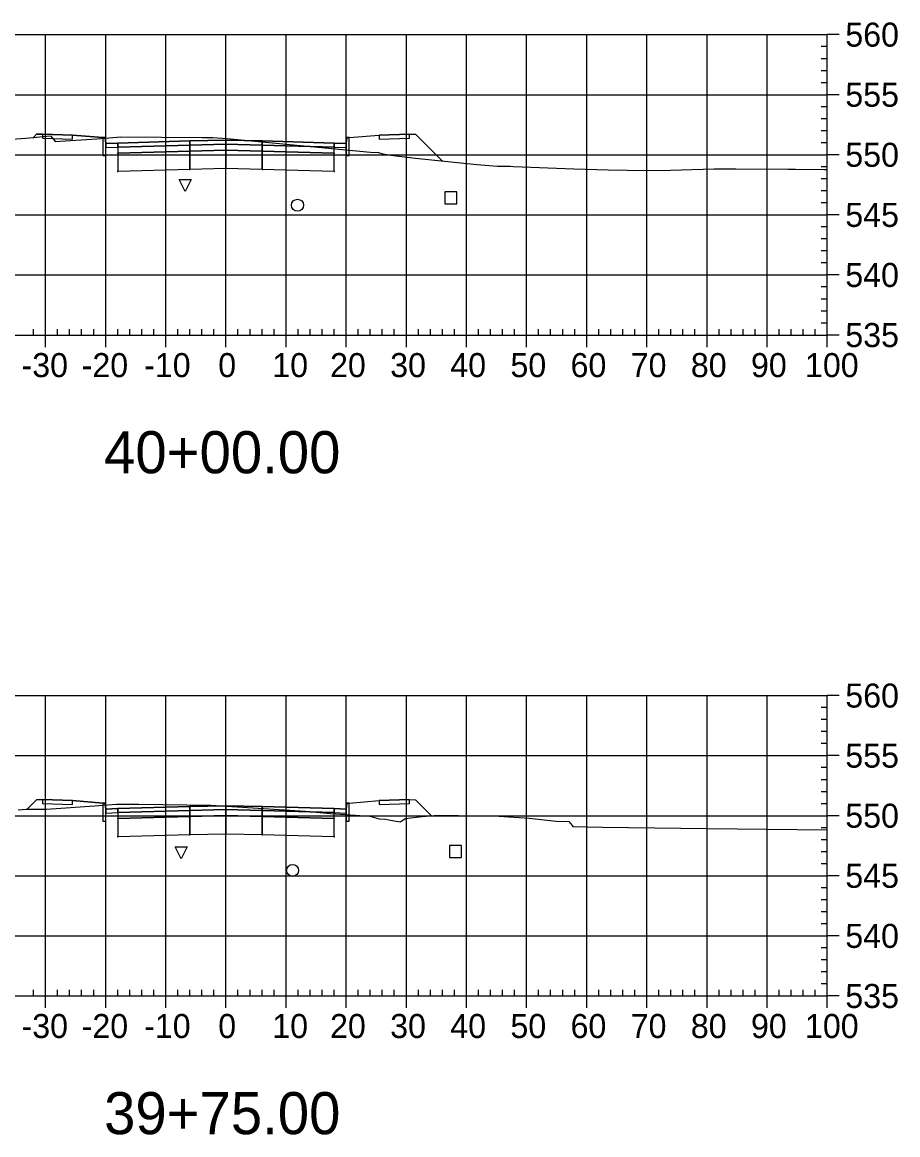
# Model space of a CAD drawing. Extents: x 704834 to 709892, y 372981 to 377533.
# Drawn here: x 709746 to 709891.6, y 376347.7 to 376532.9 of the extents above; entities that cross this region are included whole.
import ezdxf

# ---------------------------------------------------------------- set-up
doc = ezdxf.new("R2010")
doc.units = 0
for name, color, linetype in [('1', 7, 'Continuous'), ('13', 7, 'Continuous'), ('14', 7, 'Continuous'), ('4', 7, 'Continuous'), ('57', 7, 'Continuous'), ('Default_Xsect', 7, 'Continuous'), ('Existing', 7, 'Continuous')]:
    doc.layers.add(name, color=color, linetype=linetype)

msp = doc.modelspace()

# ---------------------------------------------------------------- linework, layer by layer
for points in [[(709748.41, 376514.24), (709747.88, 376513.71)], [(709749.41, 376514.28), (709748.41, 376514.24)], [(709759.41, 376513.68), (709754.41, 376514.08)], [(709800.41, 376513.68), (709805.41, 376514.08)], [(709810.41, 376514.28), (709811.41, 376514.24)], [(709811.41, 376514.24), (709815.85, 376509.81)], [(709748.41, 376403.49), (709746.84, 376401.92)], [(709749.41, 376403.53), (709748.41, 376403.49)], [(709759.41, 376402.93), (709754.41, 376403.33)], [(709800.41, 376402.93), (709805.41, 376403.33)], [(709810.41, 376403.53), (709811.41, 376403.49)], [(709811.41, 376403.49), (709814.1, 376400.81)]]:
    msp.add_lwpolyline(points)
for points in [[(709754.41, 376514.08), (709749.41, 376514.28), (709749.41, 376513.61), (709754.41, 376513.41)], [(709759.91, 376512.68), (709759.83, 376513.68), (709759.41, 376513.68), (709759.41, 376510.68), (709759.91, 376510.68)], [(709799.91, 376510.68), (709800.41, 376510.68), (709800.41, 376513.68), (709800, 376513.68), (709799.91, 376512.68)], [(709805.41, 376513.41), (709810.41, 376513.61), (709810.41, 376514.28), (709805.41, 376514.08)], [(709761.91, 376512.76), (709759.91, 376512.68), (709759.91, 376512.01), (709761.91, 376512.09)], [(709773.91, 376513.12), (709761.91, 376512.76), (709761.91, 376512.09), (709773.91, 376512.45)], [(709773.91, 376512.45), (709761.91, 376512.09), (709761.91, 376511.09), (709773.91, 376511.45)], [(709773.86, 376512.4), (709773.96, 376512.4), (709773.96, 376512.5), (709773.86, 376512.5)], [(709779.91, 376513.24), (709773.91, 376513.12), (709773.91, 376512.45), (709779.91, 376512.57)], [(709779.91, 376512.57), (709773.91, 376512.45), (709773.91, 376511.45), (709779.91, 376511.57)], [(709779.91, 376511.57), (709773.91, 376511.45), (709773.91, 376508.45), (709779.91, 376508.57)], [(709779.86, 376512.52), (709779.96, 376512.52), (709779.96, 376512.62), (709779.86, 376512.62)], [(709779.86, 376511.52), (709779.96, 376511.52), (709779.96, 376511.62), (709779.86, 376511.62)], [(709779.91, 376512.57), (709785.91, 376512.45), (709785.91, 376513.12), (709779.91, 376513.24)], [(709779.91, 376511.57), (709785.91, 376511.45), (709785.91, 376512.45), (709779.91, 376512.57)], [(709779.91, 376508.57), (709785.91, 376508.45), (709785.91, 376511.45), (709779.91, 376511.57)], [(709785.86, 376512.4), (709785.96, 376512.4), (709785.96, 376512.5), (709785.86, 376512.5)], [(709785.91, 376512.45), (709797.91, 376512.09), (709797.91, 376512.76), (709785.91, 376513.12)], [(709785.91, 376511.45), (709797.91, 376511.09), (709797.91, 376512.09), (709785.91, 376512.45)], [(709797.91, 376512.09), (709799.91, 376512.01), (709799.91, 376512.68), (709797.91, 376512.76)], [(709761.86, 376511.04), (709761.96, 376511.04), (709761.96, 376511.14), (709761.86, 376511.14)], [(709773.91, 376511.45), (709761.91, 376511.09), (709761.91, 376508.09), (709773.91, 376508.45)], [(709773.86, 376511.4), (709773.96, 376511.4), (709773.96, 376511.5), (709773.86, 376511.5)], [(709785.86, 376511.4), (709785.96, 376511.4), (709785.96, 376511.5), (709785.86, 376511.5)], [(709785.91, 376508.45), (709797.91, 376508.09), (709797.91, 376511.09), (709785.91, 376511.45)], [(709797.86, 376511.04), (709797.96, 376511.04), (709797.96, 376511.14), (709797.86, 376511.14)], [(709761.86, 376508.04), (709761.96, 376508.04), (709761.96, 376508.14), (709761.86, 376508.14)], [(709773.86, 376508.4), (709773.96, 376508.4), (709773.96, 376508.5), (709773.86, 376508.5)], [(709779.86, 376508.52), (709779.96, 376508.52), (709779.96, 376508.62), (709779.86, 376508.62)], [(709785.86, 376508.4), (709785.96, 376508.4), (709785.96, 376508.5), (709785.86, 376508.5)], [(709797.86, 376508.04), (709797.96, 376508.04), (709797.96, 376508.14), (709797.86, 376508.14)], [(709754.41, 376403.33), (709749.41, 376403.53), (709749.41, 376402.87), (709754.41, 376402.67)], [(709759.91, 376401.93), (709759.83, 376402.93), (709759.41, 376402.93), (709759.41, 376399.93), (709759.91, 376399.93)], [(709773.91, 376402.37), (709761.91, 376402.01), (709761.91, 376401.35), (709773.91, 376401.71)], [(709779.91, 376402.49), (709773.91, 376402.37), (709773.91, 376401.71), (709779.91, 376401.83)], [(709779.91, 376401.83), (709785.91, 376401.71), (709785.91, 376402.37), (709779.91, 376402.49)], [(709785.91, 376401.71), (709797.91, 376401.35), (709797.91, 376402.01), (709785.91, 376402.37)], [(709799.91, 376399.93), (709800.41, 376399.93), (709800.41, 376402.93), (709800, 376402.93), (709799.91, 376401.93)], [(709805.41, 376402.67), (709810.41, 376402.87), (709810.41, 376403.53), (709805.41, 376403.33)], [(709761.91, 376402.01), (709759.91, 376401.93), (709759.91, 376401.27), (709761.91, 376401.35)], [(709773.91, 376401.71), (709761.91, 376401.35), (709761.91, 376400.35), (709773.91, 376400.71)], [(709773.91, 376400.71), (709761.91, 376400.35), (709761.91, 376397.35), (709773.91, 376397.71)], [(709773.86, 376401.66), (709773.96, 376401.66), (709773.96, 376401.76), (709773.86, 376401.76)], [(709773.86, 376400.66), (709773.96, 376400.66), (709773.96, 376400.76), (709773.86, 376400.76)], [(709779.91, 376401.83), (709773.91, 376401.71), (709773.91, 376400.71), (709779.91, 376400.83)], [(709779.91, 376400.83), (709773.91, 376400.71), (709773.91, 376397.71), (709779.91, 376397.83)], [(709779.86, 376401.78), (709779.96, 376401.78), (709779.96, 376401.88), (709779.86, 376401.88)], [(709779.86, 376400.78), (709779.96, 376400.78), (709779.96, 376400.88), (709779.86, 376400.88)], [(709779.91, 376400.83), (709785.91, 376400.71), (709785.91, 376401.71), (709779.91, 376401.83)], [(709779.91, 376397.83), (709785.91, 376397.71), (709785.91, 376400.71), (709779.91, 376400.83)], [(709785.86, 376401.66), (709785.96, 376401.66), (709785.96, 376401.76), (709785.86, 376401.76)], [(709785.86, 376400.66), (709785.96, 376400.66), (709785.96, 376400.76), (709785.86, 376400.76)], [(709785.91, 376400.71), (709797.91, 376400.35), (709797.91, 376401.35), (709785.91, 376401.71)], [(709785.91, 376397.71), (709797.91, 376397.35), (709797.91, 376400.35), (709785.91, 376400.71)], [(709797.91, 376401.35), (709799.91, 376401.27), (709799.91, 376401.93), (709797.91, 376402.01)], [(709761.86, 376400.3), (709761.96, 376400.3), (709761.96, 376400.4), (709761.86, 376400.4)], [(709797.86, 376400.3), (709797.96, 376400.3), (709797.96, 376400.4), (709797.86, 376400.4)], [(709761.86, 376397.3), (709761.96, 376397.3), (709761.96, 376397.4), (709761.86, 376397.4)], [(709773.86, 376397.66), (709773.96, 376397.66), (709773.96, 376397.76), (709773.86, 376397.76)], [(709779.86, 376397.78), (709779.96, 376397.78), (709779.96, 376397.88), (709779.86, 376397.88)], [(709785.86, 376397.66), (709785.96, 376397.66), (709785.96, 376397.76), (709785.86, 376397.76)], [(709797.86, 376397.3), (709797.96, 376397.3), (709797.96, 376397.4), (709797.86, 376397.4)]]:
    msp.add_lwpolyline(points, close=True)
at = {"layer": '1'}
for points in [[(709773.12, 376504.73), (709772.12, 376506.73), (709774.12, 376506.73)], [(709772.47, 376393.64), (709771.47, 376395.64), (709773.47, 376395.64)]]:
    msp.add_lwpolyline(points, close=True, dxfattribs=at)
at = {"layer": '13'}
for centre in [(709791.8, 376502.43), (709790.99, 376391.72)]:
    msp.add_circle(centre, 1, dxfattribs=at)
at = {"layer": '14'}
for points in [[(709747.88, 376513.71), (709747.88, 376513.76), (709747.88, 376513.71), (709747.83, 376513.71), (709747.88, 376513.71), (709747.88, 376513.66), (709747.88, 376513.71), (709747.93, 376513.71)], [(709761.91, 376512.76), (709761.91, 376512.81), (709761.91, 376512.76), (709761.86, 376512.76), (709761.91, 376512.76), (709761.91, 376512.71), (709761.91, 376512.76), (709761.96, 376512.76)], [(709779.91, 376513.24), (709779.91, 376513.29), (709779.91, 376513.24), (709779.86, 376513.24), (709779.91, 376513.24), (709779.91, 376513.19), (709779.91, 376513.24), (709779.96, 376513.24)], [(709797.91, 376512.76), (709797.91, 376512.81), (709797.91, 376512.76), (709797.86, 376512.76), (709797.91, 376512.76), (709797.91, 376512.71), (709797.91, 376512.76), (709797.96, 376512.76)], [(709815.85, 376509.81), (709815.85, 376509.86), (709815.85, 376509.81), (709815.8, 376509.81), (709815.85, 376509.81), (709815.85, 376509.76), (709815.85, 376509.81), (709815.9, 376509.81)], [(709779.91, 376402.49), (709779.91, 376402.54), (709779.91, 376402.49), (709779.86, 376402.49), (709779.91, 376402.49), (709779.91, 376402.44), (709779.91, 376402.49), (709779.96, 376402.49)], [(709746.84, 376401.92), (709746.84, 376401.97), (709746.84, 376401.92), (709746.79, 376401.92), (709746.84, 376401.92), (709746.84, 376401.87), (709746.84, 376401.92), (709746.89, 376401.92)], [(709761.91, 376402.01), (709761.91, 376402.06), (709761.91, 376402.01), (709761.86, 376402.01), (709761.91, 376402.01), (709761.91, 376401.96), (709761.91, 376402.01), (709761.96, 376402.01)], [(709797.91, 376402.01), (709797.91, 376402.06), (709797.91, 376402.01), (709797.86, 376402.01), (709797.91, 376402.01), (709797.91, 376401.96), (709797.91, 376402.01), (709797.96, 376402.01)], [(709814.1, 376400.81), (709814.1, 376400.86), (709814.1, 376400.81), (709814.05, 376400.81), (709814.1, 376400.81), (709814.1, 376400.76), (709814.1, 376400.81), (709814.15, 376400.81)]]:
    msp.add_lwpolyline(points, dxfattribs=at)
at = {"layer": '4'}
for points in [[(709816.29, 376502.66), (709818.29, 376502.66), (709818.29, 376504.66), (709816.29, 376504.66)], [(709817.09, 376393.86), (709819.09, 376393.86), (709819.09, 376395.86), (709817.09, 376395.86)]]:
    msp.add_lwpolyline(points, close=True, dxfattribs=at)
at = {"layer": '57'}
for p, q in [((709679.91, 376530.82), (709879.91, 376530.82)), ((709749.91, 376480.82), (709749.91, 376530.82)), ((709759.91, 376480.82), (709759.91, 376530.82)), ((709769.91, 376480.82), (709769.91, 376530.82)), ((709779.91, 376480.82), (709779.91, 376530.82)), ((709789.91, 376480.82), (709789.91, 376530.82)), ((709799.91, 376480.82), (709799.91, 376530.82)), ((709809.91, 376480.82), (709809.91, 376530.82)), ((709819.91, 376480.82), (709819.91, 376530.82)), ((709829.91, 376480.82), (709829.91, 376530.82)), ((709839.91, 376480.82), (709839.91, 376530.82)), ((709849.91, 376480.82), (709849.91, 376530.82)), ((709859.91, 376480.82), (709859.91, 376530.82)), ((709869.91, 376480.82), (709869.91, 376530.82)), ((709879.91, 376480.82), (709879.91, 376530.82)), ((709879.91, 376480.82), (709879.91, 376530.82)), ((709881.91, 376530.82), (709879.91, 376530.82)), ((709879.91, 376528.82), (709878.91, 376528.82)), ((709879.91, 376526.82), (709878.91, 376526.82)), ((709879.91, 376524.82), (709878.91, 376524.82)), ((709879.91, 376522.82), (709878.91, 376522.82)), ((709679.91, 376520.82), (709879.91, 376520.82)), ((709881.91, 376520.82), (709879.91, 376520.82)), ((709879.91, 376518.82), (709878.91, 376518.82)), ((709879.91, 376516.82), (709878.91, 376516.82)), ((709879.91, 376514.82), (709878.91, 376514.82)), ((709879.91, 376512.82), (709878.91, 376512.82)), ((709679.91, 376510.82), (709879.91, 376510.82)), ((709881.91, 376510.82), (709879.91, 376510.82)), ((709879.91, 376508.82), (709878.91, 376508.82)), ((709879.91, 376506.82), (709878.91, 376506.82)), ((709879.91, 376504.82), (709878.91, 376504.82)), ((709879.91, 376502.82), (709878.91, 376502.82)), ((709679.91, 376500.82), (709879.91, 376500.82)), ((709881.91, 376500.82), (709879.91, 376500.82)), ((709879.91, 376498.82), (709878.91, 376498.82)), ((709879.91, 376496.82), (709878.91, 376496.82)), ((709879.91, 376494.82), (709878.91, 376494.82)), ((709879.91, 376492.82), (709878.91, 376492.82)), ((709679.91, 376490.82), (709879.91, 376490.82)), ((709881.91, 376490.82), (709879.91, 376490.82)), ((709879.91, 376488.82), (709878.91, 376488.82)), ((709879.91, 376486.82), (709878.91, 376486.82)), ((709879.91, 376484.82), (709878.91, 376484.82)), ((709879.91, 376482.82), (709878.91, 376482.82)), ((709679.91, 376480.82), (709879.91, 376480.82)), ((709679.91, 376480.82), (709879.91, 376480.82)), ((709747.91, 376480.82), (709747.91, 376481.82)), ((709749.91, 376478.82), (709749.91, 376480.82)), ((709751.91, 376480.82), (709751.91, 376481.82)), ((709753.91, 376480.82), (709753.91, 376481.82)), ((709755.91, 376480.82), (709755.91, 376481.82)), ((709757.91, 376480.82), (709757.91, 376481.82)), ((709759.91, 376478.82), (709759.91, 376480.82)), ((709761.91, 376480.82), (709761.91, 376481.82)), ((709763.91, 376480.82), (709763.91, 376481.82)), ((709765.91, 376480.82), (709765.91, 376481.82)), ((709767.91, 376480.82), (709767.91, 376481.82)), ((709769.91, 376478.82), (709769.91, 376480.82)), ((709771.91, 376480.82), (709771.91, 376481.82)), ((709773.91, 376480.82), (709773.91, 376481.82)), ((709775.91, 376480.82), (709775.91, 376481.82)), ((709777.91, 376480.82), (709777.91, 376481.82)), ((709779.91, 376478.82), (709779.91, 376480.82)), ((709781.91, 376480.82), (709781.91, 376481.82)), ((709783.91, 376480.82), (709783.91, 376481.82)), ((709785.91, 376480.82), (709785.91, 376481.82)), ((709787.91, 376480.82), (709787.91, 376481.82)), ((709789.91, 376478.82), (709789.91, 376480.82)), ((709791.91, 376480.82), (709791.91, 376481.82)), ((709793.91, 376480.82), (709793.91, 376481.82)), ((709795.91, 376480.82), (709795.91, 376481.82)), ((709797.91, 376480.82), (709797.91, 376481.82)), ((709799.91, 376478.82), (709799.91, 376480.82)), ((709801.91, 376480.82), (709801.91, 376481.82)), ((709803.91, 376480.82), (709803.91, 376481.82)), ((709805.91, 376480.82), (709805.91, 376481.82)), ((709807.91, 376480.82), (709807.91, 376481.82)), ((709809.91, 376478.82), (709809.91, 376480.82)), ((709811.91, 376480.82), (709811.91, 376481.82)), ((709813.91, 376480.82), (709813.91, 376481.82)), ((709815.91, 376480.82), (709815.91, 376481.82)), ((709817.91, 376480.82), (709817.91, 376481.82)), ((709819.91, 376478.82), (709819.91, 376480.82)), ((709821.91, 376480.82), (709821.91, 376481.82)), ((709823.91, 376480.82), (709823.91, 376481.82)), ((709825.91, 376480.82), (709825.91, 376481.82)), ((709827.91, 376480.82), (709827.91, 376481.82)), ((709829.91, 376478.82), (709829.91, 376480.82)), ((709831.91, 376480.82), (709831.91, 376481.82)), ((709833.91, 376480.82), (709833.91, 376481.82)), ((709835.91, 376480.82), (709835.91, 376481.82)), ((709837.91, 376480.82), (709837.91, 376481.82)), ((709839.91, 376478.82), (709839.91, 376480.82)), ((709841.91, 376480.82), (709841.91, 376481.82)), ((709843.91, 376480.82), (709843.91, 376481.82)), ((709845.91, 376480.82), (709845.91, 376481.82)), ((709847.91, 376480.82), (709847.91, 376481.82)), ((709849.91, 376478.82), (709849.91, 376480.82)), ((709851.91, 376480.82), (709851.91, 376481.82)), ((709853.91, 376480.82), (709853.91, 376481.82)), ((709855.91, 376480.82), (709855.91, 376481.82)), ((709857.91, 376480.82), (709857.91, 376481.82)), ((709859.91, 376478.82), (709859.91, 376480.82)), ((709861.91, 376480.82), (709861.91, 376481.82)), ((709863.91, 376480.82), (709863.91, 376481.82)), ((709865.91, 376480.82), (709865.91, 376481.82)), ((709867.91, 376480.82), (709867.91, 376481.82)), ((709869.91, 376478.82), (709869.91, 376480.82)), ((709871.91, 376480.82), (709871.91, 376481.82)), ((709873.91, 376480.82), (709873.91, 376481.82)), ((709875.91, 376480.82), (709875.91, 376481.82)), ((709877.91, 376480.82), (709877.91, 376481.82)), ((709879.91, 376478.82), (709879.91, 376480.82)), ((709881.91, 376480.82), (709879.91, 376480.82)), ((709679.91, 376420.82), (709879.91, 376420.82)), ((709749.91, 376370.82), (709749.91, 376420.82)), ((709759.91, 376370.82), (709759.91, 376420.82)), ((709769.91, 376370.82), (709769.91, 376420.82)), ((709779.91, 376370.82), (709779.91, 376420.82)), ((709789.91, 376370.82), (709789.91, 376420.82)), ((709799.91, 376370.82), (709799.91, 376420.82)), ((709809.91, 376370.82), (709809.91, 376420.82)), ((709819.91, 376370.82), (709819.91, 376420.82)), ((709829.91, 376370.82), (709829.91, 376420.82)), ((709839.91, 376370.82), (709839.91, 376420.82)), ((709849.91, 376370.82), (709849.91, 376420.82)), ((709859.91, 376370.82), (709859.91, 376420.82)), ((709869.91, 376370.82), (709869.91, 376420.82)), ((709879.91, 376370.82), (709879.91, 376420.82)), ((709879.91, 376370.82), (709879.91, 376420.82)), ((709881.91, 376420.82), (709879.91, 376420.82)), ((709879.91, 376418.82), (709878.91, 376418.82)), ((709879.91, 376416.82), (709878.91, 376416.82)), ((709879.91, 376414.82), (709878.91, 376414.82)), ((709879.91, 376412.82), (709878.91, 376412.82)), ((709679.91, 376410.82), (709879.91, 376410.82)), ((709881.91, 376410.82), (709879.91, 376410.82)), ((709879.91, 376408.82), (709878.91, 376408.82)), ((709879.91, 376406.82), (709878.91, 376406.82)), ((709879.91, 376404.82), (709878.91, 376404.82)), ((709879.91, 376402.82), (709878.91, 376402.82)), ((709679.91, 376400.82), (709879.91, 376400.82)), ((709881.91, 376400.82), (709879.91, 376400.82)), ((709879.91, 376398.82), (709878.91, 376398.82)), ((709879.91, 376396.82), (709878.91, 376396.82)), ((709879.91, 376394.82), (709878.91, 376394.82)), ((709879.91, 376392.82), (709878.91, 376392.82)), ((709679.91, 376390.82), (709879.91, 376390.82)), ((709881.91, 376390.82), (709879.91, 376390.82)), ((709879.91, 376388.82), (709878.91, 376388.82)), ((709879.91, 376386.82), (709878.91, 376386.82)), ((709879.91, 376384.82), (709878.91, 376384.82)), ((709879.91, 376382.82), (709878.91, 376382.82)), ((709679.91, 376380.82), (709879.91, 376380.82)), ((709881.91, 376380.82), (709879.91, 376380.82)), ((709879.91, 376378.82), (709878.91, 376378.82)), ((709879.91, 376376.82), (709878.91, 376376.82)), ((709879.91, 376374.82), (709878.91, 376374.82)), ((709879.91, 376372.82), (709878.91, 376372.82)), ((709679.91, 376370.82), (709879.91, 376370.82)), ((709679.91, 376370.82), (709879.91, 376370.82)), ((709747.91, 376370.82), (709747.91, 376371.82)), ((709749.91, 376368.82), (709749.91, 376370.82)), ((709751.91, 376370.82), (709751.91, 376371.82)), ((709753.91, 376370.82), (709753.91, 376371.82)), ((709755.91, 376370.82), (709755.91, 376371.82)), ((709757.91, 376370.82), (709757.91, 376371.82)), ((709759.91, 376368.82), (709759.91, 376370.82)), ((709761.91, 376370.82), (709761.91, 376371.82)), ((709763.91, 376370.82), (709763.91, 376371.82)), ((709765.91, 376370.82), (709765.91, 376371.82)), ((709767.91, 376370.82), (709767.91, 376371.82)), ((709769.91, 376368.82), (709769.91, 376370.82)), ((709771.91, 376370.82), (709771.91, 376371.82)), ((709773.91, 376370.82), (709773.91, 376371.82)), ((709775.91, 376370.82), (709775.91, 376371.82)), ((709777.91, 376370.82), (709777.91, 376371.82)), ((709779.91, 376368.82), (709779.91, 376370.82)), ((709781.91, 376370.82), (709781.91, 376371.82)), ((709783.91, 376370.82), (709783.91, 376371.82)), ((709785.91, 376370.82), (709785.91, 376371.82)), ((709787.91, 376370.82), (709787.91, 376371.82)), ((709789.91, 376368.82), (709789.91, 376370.82)), ((709791.91, 376370.82), (709791.91, 376371.82)), ((709793.91, 376370.82), (709793.91, 376371.82)), ((709795.91, 376370.82), (709795.91, 376371.82)), ((709797.91, 376370.82), (709797.91, 376371.82)), ((709799.91, 376368.82), (709799.91, 376370.82)), ((709801.91, 376370.82), (709801.91, 376371.82)), ((709803.91, 376370.82), (709803.91, 376371.82)), ((709805.91, 376370.82), (709805.91, 376371.82)), ((709807.91, 376370.82), (709807.91, 376371.82)), ((709809.91, 376368.82), (709809.91, 376370.82)), ((709811.91, 376370.82), (709811.91, 376371.82)), ((709813.91, 376370.82), (709813.91, 376371.82)), ((709815.91, 376370.82), (709815.91, 376371.82)), ((709817.91, 376370.82), (709817.91, 376371.82)), ((709819.91, 376368.82), (709819.91, 376370.82)), ((709821.91, 376370.82), (709821.91, 376371.82)), ((709823.91, 376370.82), (709823.91, 376371.82)), ((709825.91, 376370.82), (709825.91, 376371.82)), ((709827.91, 376370.82), (709827.91, 376371.82)), ((709829.91, 376368.82), (709829.91, 376370.82)), ((709831.91, 376370.82), (709831.91, 376371.82)), ((709833.91, 376370.82), (709833.91, 376371.82)), ((709835.91, 376370.82), (709835.91, 376371.82)), ((709837.91, 376370.82), (709837.91, 376371.82)), ((709839.91, 376368.82), (709839.91, 376370.82)), ((709841.91, 376370.82), (709841.91, 376371.82)), ((709843.91, 376370.82), (709843.91, 376371.82)), ((709845.91, 376370.82), (709845.91, 376371.82)), ((709847.91, 376370.82), (709847.91, 376371.82)), ((709849.91, 376368.82), (709849.91, 376370.82)), ((709851.91, 376370.82), (709851.91, 376371.82)), ((709853.91, 376370.82), (709853.91, 376371.82)), ((709855.91, 376370.82), (709855.91, 376371.82)), ((709857.91, 376370.82), (709857.91, 376371.82)), ((709859.91, 376368.82), (709859.91, 376370.82)), ((709861.91, 376370.82), (709861.91, 376371.82)), ((709863.91, 376370.82), (709863.91, 376371.82)), ((709865.91, 376370.82), (709865.91, 376371.82)), ((709867.91, 376370.82), (709867.91, 376371.82)), ((709869.91, 376368.82), (709869.91, 376370.82)), ((709871.91, 376370.82), (709871.91, 376371.82)), ((709873.91, 376370.82), (709873.91, 376371.82)), ((709875.91, 376370.82), (709875.91, 376371.82)), ((709877.91, 376370.82), (709877.91, 376371.82)), ((709879.91, 376368.82), (709879.91, 376370.82)), ((709881.91, 376370.82), (709879.91, 376370.82))]:
    msp.add_line(p, q, dxfattribs=at)
at = {"layer": 'Default_Xsect'}
for points in [[(709747.88, 376513.71), (709748.41, 376514.24), (709749.41, 376514.28), (709754.41, 376514.08), (709759.41, 376513.68), (709759.83, 376513.68), (709759.91, 376512.68), (709761.91, 376512.76), (709773.91, 376513.12), (709779.91, 376513.24), (709785.91, 376513.12), (709797.91, 376512.76), (709799.91, 376512.68), (709800, 376513.68), (709800.41, 376513.68), (709805.41, 376514.08), (709810.41, 376514.28), (709811.41, 376514.24), (709815.85, 376509.81)], [(709746.84, 376401.92), (709748.41, 376403.49), (709749.41, 376403.53), (709754.41, 376403.33), (709759.41, 376402.93), (709759.83, 376402.93), (709759.91, 376401.93), (709761.91, 376402.01), (709773.91, 376402.37), (709779.91, 376402.49), (709785.91, 376402.37), (709797.91, 376402.01), (709799.91, 376401.93), (709800, 376402.93), (709800.41, 376402.93), (709805.41, 376403.33), (709810.41, 376403.53), (709811.41, 376403.49), (709814.1, 376400.81)]]:
    msp.add_lwpolyline(points, dxfattribs=at)
at = {"layer": 'Existing'}
for points in [[(709742.79, 376513.3), (709746.61, 376513.59), (709750.72, 376513.99), (709751.41, 376513.18), (709751.52, 376513.01), (709752.31, 376513.1), (709758.45, 376513.48), (709762.45, 376513.8), (709775.96, 376513.71), (709777.74, 376513.69), (709780.08, 376513.54), (709803.92, 376511.28), (709805.27, 376511.19), (709805.99, 376510.98), (709807.33, 376510.76), (709811.43, 376510.28), (709821.64, 376509.19), (709823.7, 376509.02), (709825.07, 376508.95), (709826.98, 376508.91), (709827.17, 376508.92), (709827.71, 376508.9), (709837.74, 376508.48), (709843.45, 376508.34), (709849.79, 376508.23), (709853.85, 376508.25), (709861.12, 376508.46), (709861.8, 376508.47), (709862.51, 376508.48), (709863.25, 376508.48), (709864.7, 376508.48), (709873.41, 376508.45), (709874.65, 376508.44), (709879.32, 376508.4), (709879.86, 376508.39), (709879.91, 376508.39)], [(709745.36, 376401.81), (709746.67, 376401.92), (709750.09, 376401.93), (709758.05, 376402.45), (709761.7, 376402.74), (709765.44, 376402.72), (709777.41, 376402.59), (709793.13, 376401.58), (709797.29, 376401.19), (709803.83, 376400.73), (709805.37, 376400.29), (709806.52, 376400.22), (709807.01, 376400.14), (709807.9, 376399.99), (709808.94, 376399.81), (709809.01, 376399.88), (709809.74, 376400.37), (709812.52, 376400.69), (709815.21, 376400.9), (709825.29, 376400.75), (709830.33, 376400.44), (709834.81, 376399.91), (709836.93, 376399.86), (709837.47, 376399.18), (709837.59, 376399.01), (709842.51, 376398.92), (709846.83, 376398.85), (709859.91, 376398.7), (709879.91, 376398.48)]]:
    msp.add_lwpolyline(points, dxfattribs=at)

# ---------------------------------------------------------------- texts
at = {"layer": '1'}
for s, p in [('40+00.00', (709759.64, 376457.82)), ('39+75.00', (709759.64, 376347.82))]:
    msp.add_text(s, height=7, dxfattribs=at).set_placement(p)
at = {"layer": '14'}
for p in [(709749.38, 376514.23), (709749.38, 376513.56), (709754.38, 376513.36), (709805.38, 376513.36), (709810.38, 376514.23), (709810.38, 376513.56), (709749.38, 376403.48), (709749.38, 376402.82), (709754.38, 376402.62), (709805.38, 376402.62), (709810.38, 376403.48), (709810.38, 376402.82)]:
    msp.add_text('+', height=0.1, dxfattribs=at).set_placement(p)
at = {"layer": '57'}
for s, p in [('560', (709882.91, 376528.82)), ('555', (709882.91, 376518.82)), ('550', (709882.91, 376508.82)), ('545', (709882.91, 376498.82)), ('540', (709882.91, 376488.82)), ('535', (709882.91, 376478.82)), ('-30', (709745.91, 376473.82)), ('-20', (709755.91, 376473.82)), ('-10', (709766.3, 376473.82)), ('0', (709778.62, 376473.82)), ('10', (709787.61, 376473.82)), ('20', (709797.22, 376473.82)), ('30', (709807.22, 376473.82)), ('40', (709817.22, 376473.82)), ('50', (709827.22, 376473.82)), ('60', (709837.22, 376473.82)), ('70', (709847.22, 376473.82)), ('80', (709857.22, 376473.82)), ('90', (709867.22, 376473.82)), ('100', (709876.21, 376473.82)), ('560', (709882.91, 376418.82)), ('555', (709882.91, 376408.82)), ('550', (709882.91, 376398.82)), ('545', (709882.91, 376388.82)), ('540', (709882.91, 376378.82)), ('535', (709882.91, 376368.82)), ('-30', (709745.91, 376363.82)), ('-20', (709755.91, 376363.82)), ('-10', (709766.3, 376363.82)), ('0', (709778.62, 376363.82)), ('10', (709787.61, 376363.82)), ('20', (709797.22, 376363.82)), ('30', (709807.22, 376363.82)), ('40', (709817.22, 376363.82)), ('50', (709827.22, 376363.82)), ('60', (709837.22, 376363.82)), ('70', (709847.22, 376363.82)), ('80', (709857.22, 376363.82)), ('90', (709867.22, 376363.82)), ('100', (709876.21, 376363.82))]:
    msp.add_text(s, height=4, dxfattribs=at).set_placement(p)

doc.saveas('drawing.dxf')
